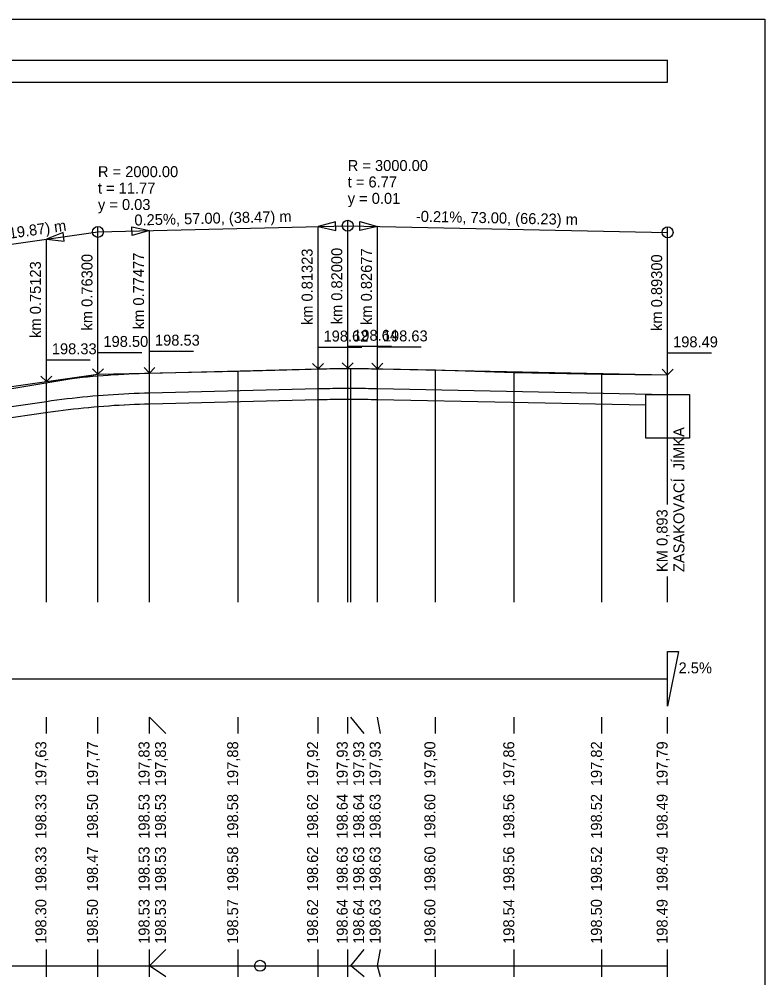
# Model space of a CAD drawing. Extents: x -51 to 53, y -74 to 15.
# Drawn here: x 36.06 to 53.08, y -6.73 to 15.15 of the extents above; entities that cross this region are included whole.
import ezdxf

# ---------------------------------------------------------------- set-up
doc = ezdxf.new("R2010")
doc.units = 0
for name, color, linetype in [('Implicitní', 7, 'Continuous'), ('KONSTRUKCE_L', 7, 'Continuous'), ('KOTY_L', 7, 'Continuous'), ('KOTY_N', 7, 'Continuous'), ('KOTY_S', 7, 'Continuous'), ('KOTY_T', 7, 'Continuous'), ('KOTY_VP', 7, 'Continuous'), ('Nová vrstva (0)', 7, 'Continuous'), ('PR_SKLON_L', 7, 'Continuous'), ('PR_SKLON_T', 7, 'Continuous'), ('ROVINA_L', 7, 'Continuous'), ('ROVINA_O', 7, 'Continuous'), ('SKLON_POMERY', 7, 'Continuous'), ('TABULKY_L', 7, 'Continuous'), ('TEREN_L', 7, 'Continuous'), ('V_POLYGON', 7, 'Continuous'), ('V_POLYGON_ZO', 7, 'Continuous')]:
    doc.layers.add(name, color=color, linetype=linetype)

msp = doc.modelspace()

# ---------------------------------------------------------------- linework, layer by layer
at = {"layer": 'Implicitní'}
msp.add_lwpolyline([(-51.392, 15.154), (53.079, 15.154), (53.079, -14.546), (-51.392, -14.546)], close=True, dxfattribs=at)
at = {"layer": 'KONSTRUKCE_L'}
for p, q in [((37.742, 6.554), (37.86, 6.564)), ((37.86, 6.564), (37.978, 6.574)), ((37.978, 6.574), (38.095, 6.582)), ((38.095, 6.582), (38.213, 6.591)), ((38.213, 6.591), (38.331, 6.598)), ((38.331, 6.598), (38.448, 6.605)), ((38.448, 6.605), (38.566, 6.611)), ((38.566, 6.611), (38.684, 6.616)), ((38.684, 6.616), (38.801, 6.621)), ((38.801, 6.621), (38.919, 6.624)), ((38.919, 6.624), (39.037, 6.628)), ((39.037, 6.628), (42.883, 6.722)), ((42.883, 6.722), (42.951, 6.724)), ((42.951, 6.724), (43.019, 6.725)), ((43.019, 6.725), (43.086, 6.726)), ((43.086, 6.726), (43.154, 6.728)), ((43.154, 6.728), (43.222, 6.729)), ((43.222, 6.729), (43.289, 6.729)), ((43.289, 6.729), (43.357, 6.73)), ((43.357, 6.73), (43.425, 6.731)), ((43.425, 6.731), (43.492, 6.731)), ((43.492, 6.731), (43.56, 6.731)), ((43.56, 6.731), (43.628, 6.731)), ((43.628, 6.731), (43.695, 6.731)), ((43.695, 6.731), (43.763, 6.731)), ((43.763, 6.731), (43.831, 6.731)), ((43.831, 6.731), (43.898, 6.73)), ((43.898, 6.73), (43.966, 6.729)), ((43.966, 6.729), (44.034, 6.728)), ((44.034, 6.728), (44.101, 6.727)), ((44.101, 6.727), (44.169, 6.726)), ((44.169, 6.726), (44.237, 6.725)), ((44.237, 6.725), (50.86, 6.589)), ((34.697, 6.149), (36.683, 6.431)), ((36.683, 6.431), (36.801, 6.448)), ((36.801, 6.448), (36.919, 6.464)), ((36.919, 6.464), (37.036, 6.479)), ((37.036, 6.479), (37.154, 6.493)), ((37.154, 6.493), (37.272, 6.506)), ((37.272, 6.506), (37.389, 6.519)), ((37.389, 6.519), (37.507, 6.532)), ((37.507, 6.532), (37.625, 6.543)), ((37.625, 6.543), (37.742, 6.554))]:
    msp.add_line(p, q, dxfattribs=at)
at = {"layer": 'KOTY_L'}
for p, q in [((37.86, 1.849), (37.86, 7.049)), ((39.037, 1.849), (39.037, 7.075)), ((39.037, 1.849), (39.037, 7.075)), ((41.06, 1.849), (41.06, 7.119)), ((42.883, 1.849), (42.883, 7.17)), ((43.56, 1.849), (43.56, 7.189)), ((43.628, 1.849), (43.628, 7.187)), ((44.237, 1.849), (44.237, 7.175)), ((45.56, 1.849), (45.56, 7.149)), ((47.36, 1.849), (47.36, 7.089)), ((49.36, 1.849), (49.36, 7.049)), ((50.86, 4.081), (50.86, 7.039)), ((36.683, 1.849), (36.683, 6.853)), ((50.86, 1.849), (50.86, 2.436)), ((36.683, -1.151), (36.683, -0.776)), ((37.86, -1.151), (37.86, -0.776)), ((39.037, -1.151), (39.037, -0.776)), ((39.412, -1.151), (39.037, -0.776)), ((41.06, -1.151), (41.06, -0.776)), ((42.883, -1.151), (42.883, -0.776)), ((43.56, -1.151), (43.56, -0.776)), ((43.935, -1.151), (43.628, -0.776)), ((44.31, -1.151), (44.237, -0.776)), ((45.56, -1.151), (45.56, -0.776)), ((47.36, -1.151), (47.36, -0.776)), ((49.36, -1.151), (49.36, -0.776)), ((50.86, -1.151), (50.86, -0.776)), ((36.683, -4.751), (36.683, -4.751)), ((37.86, -4.751), (37.86, -4.751)), ((39.037, -4.751), (39.037, -4.751)), ((39.412, -4.751), (39.412, -4.751)), ((41.06, -4.751), (41.06, -4.751)), ((42.883, -4.751), (42.883, -4.751)), ((43.56, -4.751), (43.56, -4.751)), ((43.935, -4.751), (43.935, -4.751)), ((44.31, -4.751), (44.31, -4.751)), ((45.56, -4.751), (45.56, -4.751)), ((47.36, -4.751), (47.36, -4.751)), ((49.36, -4.751), (49.36, -4.751)), ((50.86, -4.751), (50.86, -4.751)), ((36.683, -6.451), (36.683, -6.076)), ((37.86, -6.451), (37.86, -6.076)), ((39.037, -6.451), (39.037, -6.076)), ((39.037, -6.451), (39.412, -6.076)), ((41.06, -6.451), (41.06, -6.076)), ((42.883, -6.451), (42.883, -6.076)), ((43.56, -6.451), (43.56, -6.076)), ((43.628, -6.451), (43.935, -6.076)), ((44.237, -6.451), (44.31, -6.076)), ((45.56, -6.451), (45.56, -6.076)), ((47.36, -6.451), (47.36, -6.076)), ((49.36, -6.451), (49.36, -6.076)), ((50.86, -6.451), (50.86, -6.076))]:
    msp.add_line(p, q, dxfattribs=at)
at = {"layer": 'KOTY_S'}
for p, q in [((36.683, -6.701), (36.683, -6.451)), ((37.86, -6.701), (37.86, -6.451)), ((39.037, -6.701), (39.037, -6.451)), ((39.412, -6.701), (39.037, -6.451)), ((41.06, -6.701), (41.06, -6.451)), ((42.883, -6.701), (42.883, -6.451)), ((43.56, -6.701), (43.56, -6.451)), ((43.935, -6.701), (43.628, -6.451)), ((44.31, -6.701), (44.237, -6.451)), ((45.56, -6.701), (45.56, -6.451)), ((47.36, -6.701), (47.36, -6.451)), ((49.36, -6.701), (49.36, -6.451)), ((50.86, -6.701), (50.86, -6.451))]:
    msp.add_line(p, q, dxfattribs=at)
at = {"layer": 'Nová vrstva (0)'}
for p, q in [((38.229, 6.341), (38.346, 6.348)), ((38.345, 6.348), (38.463, 6.355)), ((38.461, 6.355), (38.579, 6.361)), ((38.577, 6.361), (38.695, 6.366)), ((38.693, 6.366), (38.811, 6.371)), ((38.81, 6.371), (38.927, 6.375)), ((38.926, 6.375), (39.043, 6.378)), ((39.043, 6.378), (42.889, 6.472)), ((42.889, 6.472), (42.957, 6.474)), ((42.956, 6.474), (43.024, 6.475)), ((43.023, 6.475), (43.091, 6.477)), ((43.091, 6.477), (43.158, 6.478)), ((43.158, 6.478), (43.225, 6.479)), ((43.225, 6.479), (43.292, 6.479)), ((43.292, 6.479), (43.359, 6.48)), ((43.359, 6.48), (43.427, 6.481)), ((43.426, 6.481), (43.494, 6.481)), ((43.493, 6.481), (43.561, 6.481)), ((43.56, 6.481), (43.628, 6.481)), ((43.627, 6.481), (43.695, 6.481)), ((43.694, 6.481), (43.762, 6.481)), ((43.762, 6.481), (43.829, 6.481)), ((43.829, 6.481), (43.896, 6.48)), ((43.896, 6.48), (43.963, 6.479)), ((43.963, 6.479), (44.03, 6.478)), ((44.03, 6.478), (44.098, 6.477)), ((44.097, 6.477), (44.165, 6.476)), ((44.164, 6.476), (44.232, 6.475)), ((44.232, 6.475), (50.36, 6.349)), ((34.732, 5.901), (36.719, 6.184)), ((36.718, 6.184), (36.836, 6.2)), ((36.834, 6.2), (36.952, 6.216)), ((36.95, 6.216), (37.068, 6.231)), ((37.067, 6.23), (37.184, 6.245)), ((37.183, 6.245), (37.3, 6.258)), ((37.299, 6.258), (37.417, 6.271)), ((37.415, 6.271), (37.533, 6.283)), ((37.531, 6.283), (37.649, 6.294)), ((37.648, 6.294), (37.765, 6.305)), ((37.764, 6.305), (37.882, 6.315)), ((37.88, 6.315), (37.998, 6.324)), ((37.996, 6.324), (38.114, 6.333)), ((38.112, 6.333), (38.23, 6.341))]:
    msp.add_line(p, q, dxfattribs=at)
msp.add_lwpolyline([(50.36, 6.589), (51.36, 6.589), (51.36, 5.589), (50.36, 5.589)], close=True, dxfattribs=at)
at = {"layer": 'PR_SKLON_L'}
msp.add_line((8.36, 0.099), (50.86, 0.099), dxfattribs=at)
msp.add_lwpolyline([(50.86, 0.099), (50.86, 0.724), (51.11, 0.724), (50.86, -0.526)], close=True, dxfattribs=at)
at = {"layer": 'ROVINA_L'}
msp.add_line((-38.44, -6.451), (50.86, -6.451), dxfattribs=at)
at = {"layer": 'ROVINA_O'}
msp.add_circle((41.56, -6.451), 0.125, dxfattribs=at)
at = {"layer": 'SKLON_POMERY'}
for p, q in [((43.56, 10.439), (43.56, 10.564)), ((33.36, 9.659), (37.86, 10.299)), ((37.86, 10.299), (43.56, 10.439)), ((37.86, 10.299), (37.86, 10.424)), ((37.86, 7.049), (37.86, 10.299)), ((39.037, 7.078), (39.037, 10.328)), ((42.883, 7.172), (42.883, 10.422)), ((43.56, 7.189), (43.56, 10.439)), ((43.56, 10.439), (50.86, 10.289)), ((44.237, 7.175), (44.237, 10.425)), ((50.86, 10.289), (50.86, 10.414)), ((50.86, 7.039), (50.86, 10.289)), ((36.683, 6.881), (36.683, 10.131))]:
    msp.add_line(p, q, dxfattribs=at)
for points in [[(42.883, 10.422), (43.286, 10.332), (43.281, 10.532), (42.883, 10.422)], [(44.237, 10.425), (43.835, 10.333), (43.839, 10.533), (44.237, 10.425)], [(36.683, 10.131), (37.093, 10.089), (37.065, 10.287), (36.683, 10.131)], [(39.037, 10.328), (38.639, 10.218), (38.634, 10.418), (39.037, 10.328)]]:
    msp.add_lwpolyline(points, close=True, dxfattribs=at)
for points in [[(42.758, 7.297), (42.883, 7.172), (43.008, 7.297), (42.883, 7.172), (42.883, 7.672), (43.883, 7.672)], [(43.435, 7.314), (43.56, 7.189), (43.685, 7.314), (43.56, 7.189), (43.56, 7.689), (44.56, 7.689)], [(44.112, 7.3), (44.237, 7.175), (44.362, 7.3), (44.237, 7.175), (44.237, 7.675), (45.237, 7.675)], [(37.735, 7.174), (37.86, 7.049), (37.985, 7.174), (37.86, 7.049), (37.86, 7.549), (38.86, 7.549)], [(38.912, 7.203), (39.037, 7.078), (39.162, 7.203), (39.037, 7.078), (39.037, 7.578), (40.037, 7.578)], [(50.735, 7.164), (50.86, 7.039), (50.985, 7.164), (50.86, 7.039), (50.86, 7.539), (51.86, 7.539)], [(36.558, 7.006), (36.683, 6.881), (36.808, 7.006), (36.683, 6.881), (36.683, 7.381), (37.683, 7.381)]]:
    msp.add_lwpolyline(points, dxfattribs=at)
for centre in [(43.56, 10.439), (37.86, 10.299), (50.86, 10.289)]:
    msp.add_circle(centre, 0.125, dxfattribs=at)
at = {"layer": 'TABULKY_L'}
for p, q in [((-38.44, 14.218), (50.86, 14.218)), ((50.86, 13.718), (50.86, 14.218)), ((-38.44, 13.718), (50.86, 13.718))]:
    msp.add_line(p, q, dxfattribs=at)
at = {"layer": 'TEREN_L'}
for p, q in [((35.76, 6.699), (37.86, 7.049)), ((37.86, 7.049), (41.06, 7.119)), ((41.06, 7.119), (43.56, 7.189)), ((43.56, 7.189), (45.56, 7.149)), ((45.56, 7.149), (47.36, 7.089)), ((47.36, 7.089), (49.36, 7.049)), ((49.36, 7.049), (50.86, 7.039))]:
    msp.add_line(p, q, dxfattribs=at)
at = {"layer": 'V_POLYGON'}
for p, q in [((39.037, 7.078), (42.883, 7.172)), ((44.237, 7.175), (50.86, 7.039)), ((34.697, 6.599), (36.683, 6.881))]:
    msp.add_line(p, q, dxfattribs=at)
for points in [[(36.683, 6.881), (36.801, 6.898), (36.919, 6.914), (37.036, 6.929), (37.154, 6.943), (37.272, 6.956), (37.389, 6.969), (37.507, 6.982), (37.625, 6.993), (37.742, 7.004), (37.86, 7.014), (37.978, 7.024), (38.095, 7.032), (38.213, 7.041), (38.331, 7.048), (38.448, 7.055), (38.566, 7.061), (38.684, 7.066), (38.801, 7.071), (38.919, 7.074), (39.037, 7.078)], [(42.883, 7.172), (42.951, 7.174), (43.019, 7.175), (43.086, 7.176), (43.154, 7.178), (43.222, 7.179), (43.289, 7.179), (43.357, 7.18), (43.425, 7.181), (43.492, 7.181), (43.56, 7.181), (43.628, 7.181), (43.695, 7.181), (43.763, 7.181), (43.831, 7.181), (43.898, 7.18), (43.966, 7.179), (44.034, 7.178), (44.101, 7.177), (44.169, 7.176), (44.237, 7.175)]]:
    msp.add_lwpolyline(points, dxfattribs=at)
at = {"layer": 'V_POLYGON_ZO'}
for p, q in [((36.683, 6.881), (37.86, 7.049)), ((37.86, 7.049), (39.037, 7.078)), ((42.883, 7.172), (43.56, 7.189)), ((43.56, 7.189), (44.237, 7.175))]:
    msp.add_line(p, q, dxfattribs=at)

# ---------------------------------------------------------------- texts
at = {"layer": 'KOTY_N'}
for s, p in [('198.33', (36.683, -4.751)), ('198.47', (37.86, -4.751)), ('198.53', (39.037, -4.751)), ('198.53', (39.412, -4.751)), ('198.58', (41.06, -4.751)), ('198.62', (42.883, -4.751)), ('198.63', (43.56, -4.751)), ('198.63', (43.935, -4.751)), ('198.63', (44.31, -4.751)), ('198.60', (45.56, -4.751)), ('198.56', (47.36, -4.751)), ('198.52', (49.36, -4.751)), ('198.49', (50.86, -4.751))]:
    msp.add_text(s, height=0.25, rotation=90, dxfattribs=at).set_placement(p)
at = {"layer": 'KOTY_T'}
for s, p in [('198.30', (36.683, -5.951)), ('198.50', (37.86, -5.951)), ('198.53', (39.037, -5.951)), ('198.53', (39.412, -5.951)), ('198.57', (41.06, -5.951)), ('198.62', (42.883, -5.951)), ('198.64', (43.56, -5.951)), ('198.64', (43.935, -5.951)), ('198.63', (44.31, -5.951)), ('198.60', (45.56, -5.951)), ('198.54', (47.36, -5.951)), ('198.50', (49.36, -5.951)), ('198.49', (50.86, -5.951))]:
    msp.add_text(s, height=0.25, rotation=90, dxfattribs=at).set_placement(p)
at = {"layer": 'KOTY_VP'}
for s, p in [('198.33', (36.683, -3.551)), ('198.50', (37.86, -3.551)), ('198.53', (39.037, -3.551)), ('198.53', (39.412, -3.551)), ('198.58', (41.06, -3.551)), ('198.62', (42.883, -3.551)), ('198.64', (43.56, -3.551)), ('198.64', (43.935, -3.551)), ('198.63', (44.31, -3.551)), ('198.60', (45.56, -3.551)), ('198.56', (47.36, -3.551)), ('198.52', (49.36, -3.551)), ('198.49', (50.86, -3.551))]:
    msp.add_text(s, height=0.25, rotation=90, dxfattribs=at).set_placement(p)
at = {"layer": 'Nová vrstva (0)'}
for s, p in [('ZASAKOVACÍ  JÍMKA', (51.243, 2.536)), ('KM 0,893', (50.859, 2.536)), ('197,63', (36.683, -2.351)), ('197,77', (37.86, -2.351)), ('197,83', (39.037, -2.351)), ('197,83', (39.412, -2.351)), ('197,88', (41.06, -2.351)), ('197,92', (42.883, -2.351)), ('197,93', (43.56, -2.351)), ('197,93', (43.935, -2.351)), ('197,93', (44.31, -2.351)), ('197,90', (45.56, -2.351)), ('197,86', (47.36, -2.351)), ('197,82', (49.36, -2.351)), ('197,79', (50.86, -2.351))]:
    msp.add_text(s, height=0.25, rotation=90, dxfattribs=at).set_placement(p)
at = {"layer": 'PR_SKLON_T'}
msp.add_text('2.5%', height=0.25, dxfattribs=at).set_placement((51.11, 0.224))
at = {"layer": 'SKLON_POMERY'}
for s, p in [('R = 3000.00', (43.56, 11.689)), ('R = 2000.00', (37.86, 11.549)), ('t = 11.77', (37.86, 11.174)), ('t = 6.77', (43.56, 11.314)), ('y = 0.01', (43.56, 10.939)), ('y = 0.03', (37.86, 10.799)), ('198.50', (37.985, 7.674)), ('198.53', (39.162, 7.703)), ('198.62', (43.008, 7.797)), ('198.64', (43.685, 7.814)), ('198.63', (44.362, 7.8)), ('198.49', (50.985, 7.664)), ('198.33', (36.808, 7.506))]:
    msp.add_text(s, height=0.25, dxfattribs=at).set_placement(p)
for s, rotation, p in [('0.25%, 57.00, (38.47) m', 1.407, (38.695, 10.444)), ('-0.21%, 73.00, (66.23) m', 358.8229, (45.113, 10.532)), ('1.42%, 45.00, (19.87) m', 8.0945, (33.6, 9.822)), ('km 0.81323', 90, (42.758, 8.172)), ('km 0.82000', 90, (43.435, 8.189)), ('km 0.82677', 90, (44.112, 8.175)), ('km 0.76300', 90, (37.735, 8.049)), ('km 0.77477', 90, (38.912, 8.078)), ('km 0.89300', 90, (50.735, 8.039)), ('km 0.75123', 90, (36.558, 7.881))]:
    msp.add_text(s, height=0.25, rotation=rotation, dxfattribs=at).set_placement(p)

doc.saveas('drawing.dxf')
